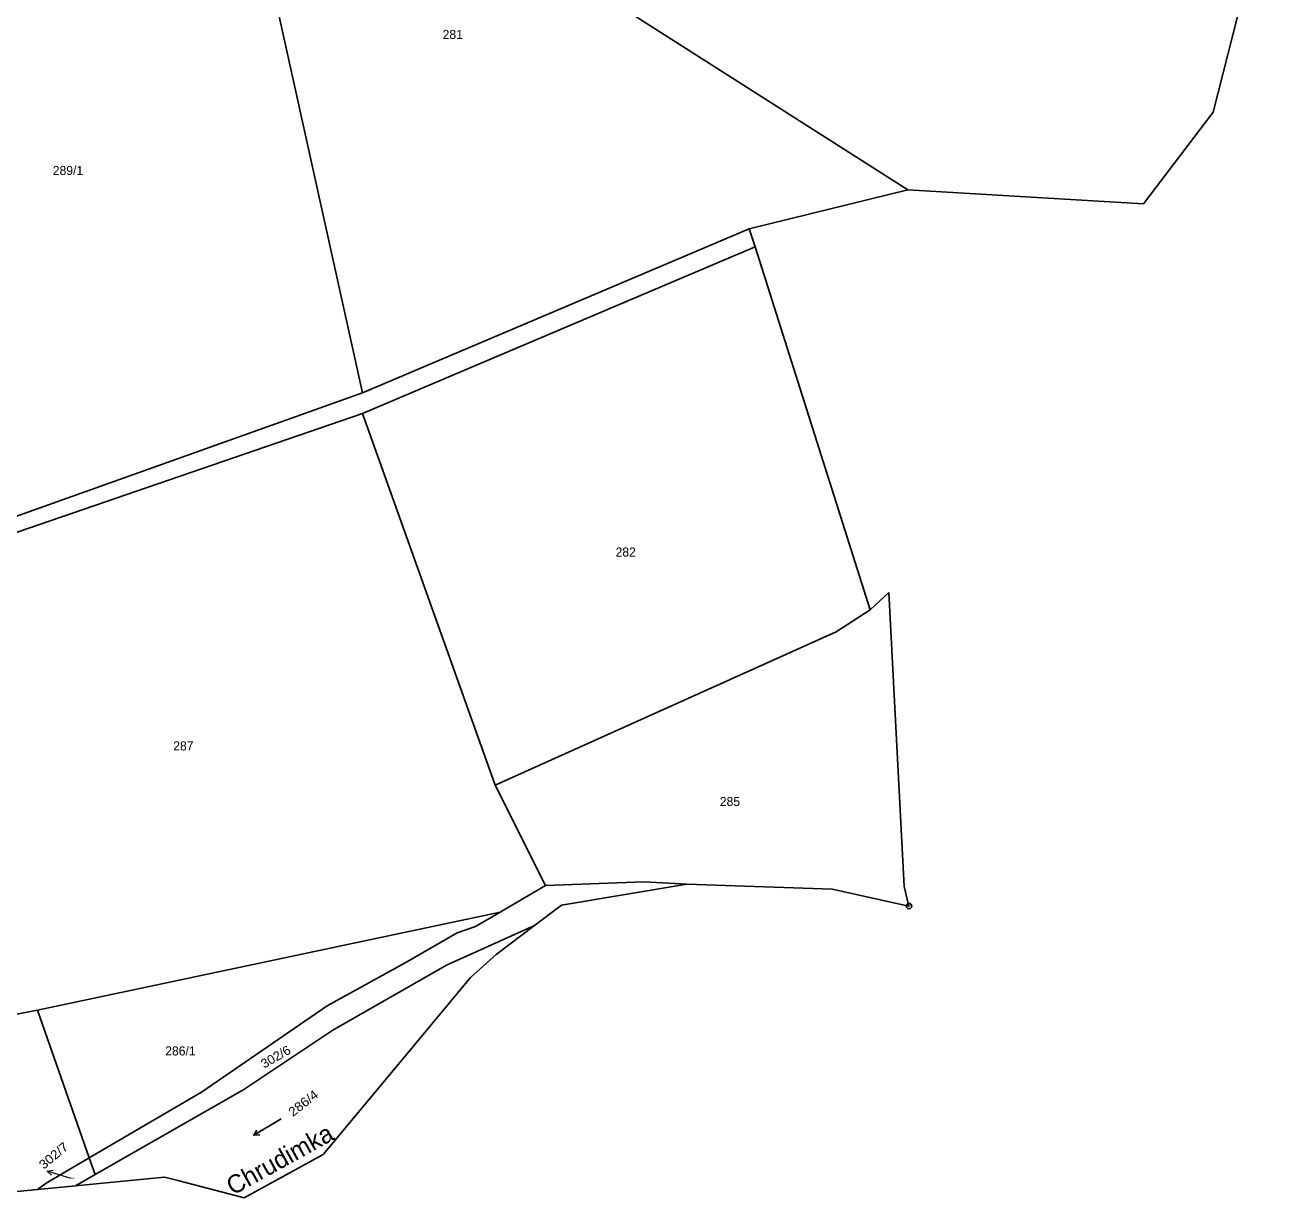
# Model space of a CAD drawing. Extents: x -645290 to -643454, y -1064771 to -1062356.
# Drawn here: x -644210.6 to -643973.7, y -1064051.6 to -1063831.9 of the extents above; entities that cross this region are included whole.
import ezdxf
from ezdxf.enums import TextEntityAlignment as Align

# ---------------------------------------------------------------- set-up
doc = ezdxf.new("R2010")
doc.units = 0
doc.header["$LTSCALE"] = 0.68
for name, color, linetype, lineweight in [('1', 7, 'Continuous', 25), ('3', 7, 'Continuous', 25), ('7', 7, 'Continuous', 13), ('8', 7, 'Continuous', 25)]:
    doc.layers.add(name, color=color, linetype=linetype, lineweight=lineweight)
doc.layers.add('2', color=7, linetype='Continuous')

msp = doc.modelspace()

# ---------------------------------------------------------------- linework, layer by layer
at = {"layer": '1'}
for p, q in [((-644175.31, -1063774.49), (-644147.42, -1063900.81)), ((-643988.03, -1063848.16), (-643973.66, -1063791.87)), ((-644099.24, -1063828.34), (-644045.21, -1063862.71)), ((-644001.03, -1063865.36), (-643988.03, -1063848.16)), ((-644074.92, -1063870.05), (-644045.21, -1063862.71)), ((-644045.21, -1063862.71), (-644001.03, -1063865.36)), ((-644147.42, -1063900.81), (-644074.92, -1063870.05)), ((-644073.84, -1063873.45), (-644074.92, -1063870.05)), ((-644073.84, -1063873.45), (-644147.41, -1063904.66)), ((-644052.3, -1063941.44), (-644073.84, -1063873.45)), ((-644147.42, -1063900.81), (-644213.45, -1063924.36)), ((-644147.41, -1063904.66), (-644240.87, -1063936.79)), ((-644147.41, -1063904.66), (-644122.56, -1063974.28)), ((-644048.77, -1063938.17), (-644052.3, -1063941.44)), ((-644045.91, -1063993.28), (-644048.77, -1063938.17)), ((-644058.62, -1063945.58), (-644052.3, -1063941.44)), ((-644122.56, -1063974.28), (-644058.62, -1063945.58)), ((-644122.56, -1063974.28), (-644113.1, -1063993.12)), ((-644113.1, -1063993.12), (-644121.62, -1063998.08)), ((-644094.61, -1063992.4), (-644113.1, -1063993.12)), ((-644110.1, -1063996.76), (-644086.6, -1063992.87)), ((-644094.61, -1063992.4), (-644086.6, -1063992.87)), ((-644086.6, -1063992.87), (-644059.4, -1063993.81)), ((-644059.4, -1063993.81), (-644045, -1063996.96)), ((-644045, -1063996.96), (-644045.91, -1063993.28)), ((-644115.19, -1064000.62), (-644110.1, -1063996.76)), ((-644208.32, -1064016.48), (-644121.62, -1063998.08)), ((-644121.62, -1063998.08), (-644126.25, -1064000.78)), ((-644115.19, -1064000.62), (-644131.65, -1064008.02)), ((-644126.25, -1064000.78), (-644129.66, -1064001.97)), ((-644122.33, -1064006.05), (-644115.19, -1064000.62)), ((-644129.66, -1064001.97), (-644139.38, -1064007.61)), ((-644127.15, -1064010.37), (-644122.33, -1064006.05)), ((-644139.38, -1064007.61), (-644154, -1064015.67)), ((-644131.65, -1064008.02), (-644152.99, -1064020.23)), ((-644141.61, -1064027.71), (-644127.15, -1064010.37)), ((-644154, -1064015.67), (-644177.6, -1064031.86)), ((-644212.87, -1064017.33), (-644208.32, -1064016.48)), ((-644208.32, -1064016.48), (-644198.6, -1064044.14)), ((-644152.99, -1064020.23), (-644169.64, -1064031.33)), ((-644154.78, -1064043.51), (-644141.61, -1064027.71)), ((-644177.6, -1064031.86), (-644198.6, -1064044.14)), ((-644169.64, -1064031.33), (-644197.5, -1064047.28)), ((-644198.6, -1064044.14), (-644206.69, -1064048.87)), ((-644198.6, -1064044.14), (-644197.5, -1064047.28)), ((-644169.55, -1064051.61), (-644154.78, -1064043.51)), ((-644206.69, -1064048.87), (-644208.31, -1064050.09)), ((-644197.5, -1064047.28), (-644201.17, -1064049.38)), ((-644201.17, -1064049.38), (-644184.5, -1064047.73)), ((-644184.5, -1064047.73), (-644181.77, -1064048.44)), ((-644181.77, -1064048.44), (-644169.55, -1064051.61)), ((-644214.67, -1064050.68), (-644208.31, -1064050.09)), ((-644208.31, -1064050.09), (-644204.39, -1064049.7)), ((-644204.39, -1064049.7), (-644201.17, -1064049.38))]:
    msp.add_line(p, q, dxfattribs=at)
at = {"layer": '3'}
msp.add_line((-644167.771, -1064039.897), (-644167.191, -1064038.964), dxfattribs=at)
msp.add_lwpolyline([(-644162.628, -1064036.806), (-644167.771, -1064039.897), (-644166.675, -1064039.823)], dxfattribs=at)
at = {"layer": '7'}
msp.add_line((-644206.49, -1064046.633), (-644205.679, -1064047.404), dxfattribs=at)
msp.add_lwpolyline([(-644201.98, -1064048.02), (-644203.62, -1064047.51), (-644206.49, -1064046.633), (-644205.386, -1064046.447)], dxfattribs=at)
at = {"layer": '8'}
for radius in [0.5, 0.0303]:
    msp.add_circle((-644045, -1063996.9599), radius, dxfattribs=at)

# ---------------------------------------------------------------- texts
at = {"layer": '2'}
for s, height, p in [('281', 1.7, (-644132.39, -1063834.475)), ('289/1', 1.7, (-644205.44, -1063859.965)), ('282', 1.7, (-644099.98, -1063931.465)), ('287', 1.7, (-644182.87, -1063967.795)), ('285', 1.7, (-644080.45, -1063978.215)), ('286/1', 1.7, (-644184.37, -1064024.955)), ('302/7', 0.2, (-644201.98, -1064048.07))]:
    msp.add_text(s, height=height, dxfattribs=at).set_placement(p)
at = {"layer": '2', "width": 1.05}
msp.add_text('302/6', height=1.7, rotation=30, dxfattribs=at).set_placement((-644165.837, -1064027.428))
at = {"layer": '2', "width": 1.1}
msp.add_text('286/4', height=1.7, rotation=38, dxfattribs=at).set_placement((-644157.9813, -1064034.5655), align=Align.CENTER)
msp.add_text('302/7', height=1.7, rotation=40, dxfattribs=at).set_placement((-644202.3497, -1064042.3684), align=Align.RIGHT)
at = {"layer": '7'}
msp.add_text('Chrudimka', height=3.4, rotation=29, dxfattribs=at).set_placement((-644162.0877, -1064045.9109), align=Align.CENTER)

doc.saveas('drawing.dxf')
